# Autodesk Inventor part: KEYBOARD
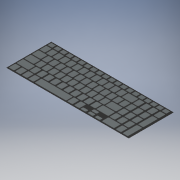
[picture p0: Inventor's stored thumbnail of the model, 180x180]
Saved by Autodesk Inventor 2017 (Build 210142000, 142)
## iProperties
Created: 2017-02
Part Number: KEYBOARD
Material: Generic
Document SubType Name: Modeling
Designer: Ali
Density: 1 g/cm^3
Appearance: Default
Author: Ali
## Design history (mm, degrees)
sketch "Sketch1"
  geometry: L1 (149.99, -109.99)-(-149.99, -109.99); L2 (-149.99, -109.99)-(-149.99, 0); L3 (-149.99, 0)-(149.99, 0); L4 (149.99, 0)-(149.99, -109.99)
  constraints: 8 end point, 2 parallel, 1 horizontal, 1 perpendicular
  dimensions: "d2" = 299.98 distance of L2.end L3.end; "d3" = 109.99 distance of L1.end L2.end
extrude "KEYBOARD BASE" new body sketch "Sketch1" distance "d4" = 0.01; taper "d5" = 0 deg
sketch "Sketch2"
  geometry: L1 (-146.991, 107.99)-(-136.991, 107.99); L2 (-135.991, 106.99)-(-135.991, 98.99); L3 (-136.991, 97.99)-(-146.991, 97.99); L4 (-147.991, 98.99)-(-147.991, 106.99); A1 r 1 centre (-146.991, 106.99) between (-146.991, 107.99) and (-147.991, 106.99); A2 r 1 centre (-136.991, 106.99) between (-135.991, 106.99) and (-136.991, 107.99); A3 r 1 centre (-136.991, 98.99) between (-136.991, 97.99) and (-135.991, 98.99); A4 r 1 centre (-146.991, 98.99) between (-147.991, 98.99) and (-146.991, 97.99); 5 further points
  constraints: 8 end point, 8 point on circle, 8 point on line, 8 tangent, 4 centre point, 3 equal radius, 2 parallel, 1 horizontal, 1 perpendicular
  dimensions: "d9" = 10 distance of point (-147.991, 97.99) point (-147.991, 107.99); "d10" = 12 distance of point (-147.991, 107.99) point (-135.991, 107.99); "d150" = 1 radius of A1 (derived)
extrude "ESCAPE BUTTON" join sketch "Sketch2" distance "d11" = 0.3; taper "d12" = 0 deg
sketch "Sketch3"
  geometry: L1 (-145.991, 95.99)-(-136.491, 95.99); L2 (-134.491, 93.99)-(-134.491, 80.79); L3 (-136.491, 78.79)-(-145.991, 78.79); L4 (-147.991, 80.79)-(-147.991, 93.99); A1 r 2 centre (-145.991, 93.99) between (-145.991, 95.99) and (-147.991, 93.99); A2 r 2 centre (-136.491, 93.99) between (-134.491, 93.99) and (-136.491, 95.99); A3 r 2 centre (-136.491, 80.79) between (-136.491, 78.79) and (-134.491, 80.79); A4 r 2 centre (-145.991, 80.79) between (-147.991, 80.79) and (-145.991, 78.79); 4 further points
  constraints: 8 end point, 8 point on circle, 8 point on line, 8 tangent, 4 centre point, 3 equal radius, 2 parallel, 1 horizontal, 1 perpendicular
  dimensions: "d19" = 13.5 distance of point (-147.991, 95.99) point (-134.491, 95.99); "d20" = 17.2 distance of point (-147.991, 78.79) point (-147.991, 95.99); "d151" = 2 radius of A1 (derived)
extrude "2ND ROW" join sketch "Sketch3" distance "d21" = 0.3; taper "d22" = 0 deg
pattern_linear "2ND ROW PATTERN" dims "d25" = 15.5
sketch "Sketch6"
  geometry: L1 (133.509, 95.99)-(143.009, 95.99); L2 (145.009, 93.99)-(145.009, 80.79); L3 (143.009, 78.79)-(133.509, 78.79); L4 (131.509, 80.79)-(131.509, 93.99); A1 r 2 centre (133.509, 93.99) between (133.509, 95.99) and (131.509, 93.99); A2 r 2 centre (143.009, 93.99) between (145.009, 93.99) and (143.009, 95.99); A3 r 2 centre (143.009, 80.79) between (143.009, 78.79) and (145.009, 80.79); A4 r 2 centre (133.509, 80.79) between (131.509, 80.79) and (133.509, 78.79); 5 further points
  constraints: 8 end point, 8 point on circle, 8 point on line, 8 tangent, 4 centre point, 3 equal radius, 2 parallel, 1 horizontal, 1 perpendicular
  dimensions: "d52" = 13.5 distance of point (145.009, 78.79) point (131.509, 78.79); "d53" = 17.2 distance of point (145.009, 95.99) point (145.009, 78.79); "d157" = 2 radius of A1 (derived)
extrude "BACKSPACE BUTTON" join sketch "Sketch6" distance "d33" = 0.3; taper "d34" = 0 deg
sketch "Sketch7"
  geometry: L1 (133.51, 76.99)-(143.01, 76.99); L2 (145.01, 74.99)-(145.01, 42.79); L3 (143.01, 40.79)-(133.51, 40.79); L4 (131.51, 42.79)-(131.51, 74.99); A1 r 2 centre (133.51, 74.99) between (133.51, 76.99) and (131.51, 74.99); A2 r 2 centre (143.01, 74.99) between (145.01, 74.99) and (143.01, 76.99); A3 r 2 centre (143.01, 42.79) between (143.01, 40.79) and (145.01, 42.79); A4 r 2 centre (133.51, 42.79) between (131.51, 42.79) and (133.51, 40.79); 5 further points
  constraints: 8 end point, 8 point on circle, 8 point on line, 8 tangent, 4 centre point, 3 equal radius, 2 parallel, 1 horizontal, 1 perpendicular
  dimensions: "d56" = 13.5 distance of point (145.01, 40.79) point (131.51, 40.79); "d57" = 36.2 distance of point (145.01, 76.99) point (145.01, 40.79); "d158" = 2 radius of A1 (derived)
extrude "NUM LOCK BUTTON" join sketch "Sketch7" distance "d38" = 0.3; taper "d39" = 0 deg
pattern_linear "NUMERIC KEYPAD" dims "d42" = 17, "d45" = 19
sketch "Sketch9"
  geometry: L1 (116.509, 19.989)-(126.009, 19.989); L2 (128.009, 17.989)-(128.009, 4.789); L3 (126.009, 2.789)-(116.509, 2.789); L4 (114.509, 4.789)-(114.509, 17.989); A1 r 2 centre (116.509, 17.989) between (116.509, 19.989) and (114.509, 17.989); A2 r 2 centre (126.009, 17.989) between (128.009, 17.989) and (126.009, 19.989); A3 r 2 centre (126.009, 4.789) between (126.009, 2.789) and (128.009, 4.789); A4 r 2 centre (116.509, 4.789) between (114.509, 4.789) and (116.509, 2.789); 5 further points
  constraints: 8 end point, 8 point on circle, 8 point on line, 8 tangent, 4 centre point, 3 equal radius, 2 parallel, 1 horizontal, 1 perpendicular
  dimensions: "d160" = 2 radius of A1 (derived)
extrude "SUBTRACT BUTTON" join sketch "Sketch9" distance "d54" = 0.3; taper "d55" = 0 deg
sketch "Sketch10"
  geometry: L1 (-145.991, 76.986)-(-127.991, 76.986); L2 (-125.991, 74.986)-(-125.991, 61.786); L3 (-127.991, 59.786)-(-145.991, 59.786); L4 (-147.991, 61.786)-(-147.991, 74.986); A1 r 2 centre (-145.991, 74.986) between (-145.991, 76.986) and (-147.991, 74.986); A2 r 2 centre (-127.991, 74.986) between (-125.991, 74.986) and (-127.991, 76.986); A3 r 2 centre (-127.991, 61.786) between (-127.991, 59.786) and (-125.991, 61.786); A4 r 2 centre (-145.991, 61.786) between (-147.991, 61.786) and (-145.991, 59.786); 4 further points
  constraints: 8 end point, 8 point on circle, 8 point on line, 8 tangent, 4 centre point, 3 equal radius, 2 parallel, 1 horizontal, 1 perpendicular
  dimensions: "d161" = 2 radius of A1 (derived)
extrude "ADD BUTTON" join sketch "Sketch10" distance "d58" = 0.3; taper "d59" = 0 deg
pattern_linear "ENTER BUTTON" dims "d62" = 38
sketch "Sketch11"
  geometry: L1 (-121.995, 76.986)-(-112.495, 76.986); L2 (-110.495, 74.986)-(-110.495, 61.786); L3 (-112.495, 59.786)-(-121.995, 59.786); L4 (-123.995, 61.786)-(-123.995, 74.986); A1 r 2 centre (-121.995, 74.986) between (-121.995, 76.986) and (-123.995, 74.986); A2 r 2 centre (-112.495, 74.986) between (-110.495, 74.986) and (-112.495, 76.986); A3 r 2 centre (-112.495, 61.786) between (-112.495, 59.786) and (-110.495, 61.786); A4 r 2 centre (-121.995, 61.786) between (-123.995, 61.786) and (-121.995, 59.786); 5 further points
  constraints: 8 end point, 8 point on circle, 8 point on line, 8 tangent, 4 centre point, 3 equal radius, 2 parallel, 1 horizontal, 1 perpendicular
  dimensions: "d153" = 2 radius of A1 (derived)
extrude "0 BUTTON" join sketch "Sketch11" distance "d65" = 0.3; taper "d66" = 0 deg
sketch "Sketch12"
  geometry: L1 (-145.991, 57.989)-(-125.991, 57.989); L2 (-123.991, 55.989)-(-123.991, 42.789); L3 (-125.991, 40.789)-(-145.991, 40.789); L4 (-147.991, 42.789)-(-147.991, 55.989); A1 r 2 centre (-145.991, 55.989) between (-145.991, 57.989) and (-147.991, 55.989); A2 r 2 centre (-145.991, 42.789) between (-147.991, 42.789) and (-145.991, 40.789); A3 r 2 centre (-125.991, 42.789) between (-125.991, 40.789) and (-123.991, 42.789); A4 r 2 centre (-125.991, 55.989) between (-123.991, 55.989) and (-125.991, 57.989); 4 further points
  constraints: 8 end point, 8 point on circle, 8 point on line, 8 tangent, 4 centre point, 3 equal radius, 2 parallel, 1 horizontal, 1 perpendicular
  dimensions: "d84" = 24 distance of point (-147.991, 57.989) point (-123.991, 57.989); "d85" = 17.2 distance of point (-147.991, 40.789) point (-147.991, 57.989); "d162" = 2 radius of A1 (derived)
extrude "DOT BUTTON" join sketch "Sketch12" distance "d69" = 0.3; taper "d70" = 0 deg
sketch "Sketch13"
  geometry: L1 (-119.996, 57.989)-(-110.496, 57.989); L2 (-108.496, 55.989)-(-108.496, 42.789); L3 (-110.496, 40.789)-(-119.996, 40.789); L4 (-121.996, 42.789)-(-121.996, 55.989); A1 r 2 centre (-119.996, 55.989) between (-119.996, 57.989) and (-121.996, 55.989); A2 r 2 centre (-110.496, 55.989) between (-108.496, 55.989) and (-110.496, 57.989); A3 r 2 centre (-110.496, 42.789) between (-110.496, 40.789) and (-108.496, 42.789); A4 r 2 centre (-119.996, 42.789) between (-121.996, 42.789) and (-119.996, 40.789); 5 further points
  constraints: 8 end point, 8 point on circle, 8 point on line, 8 tangent, 4 centre point, 3 equal radius, 2 parallel, 1 horizontal, 1 perpendicular
  dimensions: "d154" = 2 radius of A1 (derived)
extrude "TAB BUTTON" join sketch "Sketch13" distance "d73" = 0.3; taper "d74" = 0 deg
sketch "Sketch14"
  geometry: L1 (52.999, 57.989)-(75.999, 57.989); L2 (77.999, 55.989)-(77.999, 42.789); L3 (75.999, 40.789)-(52.999, 40.789); L4 (50.999, 42.789)-(50.999, 55.989); A1 r 2 centre (52.999, 55.989) between (52.999, 57.989) and (50.999, 55.989); A2 r 2 centre (75.999, 55.989) between (77.999, 55.989) and (75.999, 57.989); A3 r 2 centre (75.999, 42.789) between (75.999, 40.789) and (77.999, 42.789); A4 r 2 centre (52.999, 42.789) between (50.999, 42.789) and (52.999, 40.789); 4 further points
  constraints: 8 end point, 8 point on circle, 8 point on line, 8 tangent, 4 centre point, 3 equal radius, 2 parallel, 1 horizontal, 1 perpendicular
  dimensions: "d95" = 27 distance of point (77.999, 40.789) point (50.999, 40.789); "d96" = 17.2 distance of point (77.999, 57.989) point (77.999, 40.789); "d163" = 2 radius of A1 (derived)
extrude "Q BUTTON" join sketch "Sketch14" distance "d77" = 0.3; taper "d78" = 0 deg
pattern_linear "QWERTY" dims "d81" = 15.7
sketch "Sketch15" dims "d112" = 17.2, "d113" = 77.5, "d165" = 2 (derived)
  geometry: L1 (-145.991, 38.992)-(-119.991, 38.992); L2 (-117.991, 36.992)-(-117.991, 23.792); L3 (-119.991, 21.792)-(-145.991, 21.792); L4 (-147.991, 23.792)-(-147.991, 36.992); A1 r 2 centre (-145.991, 36.992) between (-145.991, 38.992) and (-147.991, 36.992); A2 r 2 centre (-119.991, 36.992) between (-117.991, 36.992) and (-119.991, 38.992); A3 r 2 centre (-119.991, 23.792) between (-119.991, 21.792) and (-117.991, 23.792); A4 r 2 centre (-145.991, 23.792) between (-147.991, 23.792) and (-145.991, 21.792); 4 further points
  constraints: 8 end point, 8 point on circle, 8 point on line, 8 tangent, 4 centre point, 3 equal radius, 2 parallel, 1 horizontal, 1 perpendicular
  dimensions: "d101" = 30 distance of point (-147.991, 38.992) point (-117.991, 38.992); "d102" = 17.2 distance of point (-147.991, 21.792) point (-147.991, 38.992); "d164" = 2 radius of A1 (derived)
extrude "CAPS LOCK" join sketch "Sketch15" distance "d86" = 0.3; taper "d87" = 0 deg
sketch "Sketch16"
  geometry: L1 (-113.99, 38.992)-(-104.49, 38.992); L2 (-102.49, 36.992)-(-102.49, 23.792); L3 (-104.49, 21.792)-(-113.99, 21.792); L4 (-115.99, 23.792)-(-115.99, 36.992); A1 r 2 centre (-113.99, 36.992) between (-113.99, 38.992) and (-115.99, 36.992); A2 r 2 centre (-104.49, 36.992) between (-102.49, 36.992) and (-104.49, 38.992); A3 r 2 centre (-104.49, 23.792) between (-104.49, 21.792) and (-102.49, 23.792); A4 r 2 centre (-113.99, 23.792) between (-115.99, 23.792) and (-113.99, 21.792); 5 further points
  constraints: 8 end point, 8 point on circle, 8 point on line, 8 tangent, 4 centre point, 3 equal radius, 2 parallel, 1 horizontal, 1 perpendicular
  dimensions: "d155" = 2 radius of A1 (derived)
extrude "A BUTTON" join sketch "Sketch16" distance "d90" = 0.3; taper "d91" = 0 deg
pattern_linear "ASDFGH" dims "d94" = 15.75
sketch "Sketch17"
  geometry: L1 (-81.99, 19.989)-(-8.49, 19.989); L2 (-6.49, 17.989)-(-6.49, 4.789); L3 (-8.49, 2.789)-(-81.99, 2.789); L4 (-83.99, 4.789)-(-83.99, 17.989); A1 r 2 centre (-81.99, 17.989) between (-81.99, 19.989) and (-83.99, 17.989); A2 r 2 centre (-8.49, 17.989) between (-6.49, 17.989) and (-8.49, 19.989); A3 r 2 centre (-8.49, 4.789) between (-8.49, 2.789) and (-6.49, 4.789); A4 r 2 centre (-81.99, 4.789) between (-83.99, 4.789) and (-81.99, 2.789); 4 further points
  constraints: 8 end point, 8 point on circle, 8 point on line, 8 tangent, 4 centre point, 3 equal radius, 2 parallel, 1 horizontal, 1 perpendicular
  dimensions: "d112" = 17.2 distance of point (-6.49, 19.989) point (-6.49, 2.789); "d113" = 77.5 distance of point (-6.49, 2.789) point (-83.99, 2.789); "d165" = 2 radius of A1 (derived)
extrude "ENTER BUTTON 1" join sketch "Sketch17" distance "d97" = 0.3; taper "d98" = 0 deg
sketch "Sketch18"
  geometry: L1 (75.999, 38.991)-(49.999, 38.991); L2 (47.999, 36.991)-(47.999, 23.791); L3 (49.999, 21.791)-(75.999, 21.791); L4 (77.999, 23.791)-(77.999, 36.991); A1 r 2 centre (49.999, 36.991) between (49.999, 38.991) and (47.999, 36.991); A2 r 2 centre (75.999, 36.991) between (77.999, 36.991) and (75.999, 38.991); A3 r 2 centre (75.999, 23.791) between (75.999, 21.791) and (77.999, 23.791); A4 r 2 centre (49.999, 23.791) between (47.999, 23.791) and (49.999, 21.791); 4 further points
  constraints: 8 end point, 8 point on circle, 8 point on line, 8 tangent, 4 centre point, 3 equal radius, 2 parallel, 1 horizontal, 1 perpendicular
  dimensions: "d166" = 2 radius of A1 (derived)
extrude "LEFT SHIFT" join sketch "Sketch18" distance "d103" = 0.3; taper "d104" = 0 deg
sketch "Sketch19"
  geometry: L1 (-145.991, 19.992)-(-136.491, 19.992); L2 (-134.491, 17.992)-(-134.491, 4.792); L3 (-136.491, 2.792)-(-145.991, 2.792); L4 (-147.991, 4.792)-(-147.991, 17.992); A1 r 2 centre (-145.991, 17.992) between (-145.991, 19.992) and (-147.991, 17.992); A2 r 2 centre (-136.491, 17.992) between (-134.491, 17.992) and (-136.491, 19.992); A3 r 2 centre (-136.491, 4.792) between (-136.491, 2.792) and (-134.491, 4.792); A4 r 2 centre (-145.991, 4.792) between (-147.991, 4.792) and (-145.991, 2.792); 5 further points
  constraints: 8 end point, 8 point on circle, 8 point on line, 8 tangent, 4 centre point, 3 equal radius, 2 parallel, 1 horizontal, 1 perpendicular
  dimensions: "d167" = 2 radius of A1 (derived)
extrude "Z BUTTON" join sketch "Sketch19" distance "d107" = 0.3; taper "d108" = 0 deg
pattern_linear "ZXCVBN" dims "d111" = 16.5
sketch "Sketch20"
  geometry: L1 (-2.489, 19.989)-(7.011, 19.989); L2 (9.011, 17.989)-(9.011, 4.789); L3 (7.011, 2.789)-(-2.489, 2.789); L4 (-4.489, 4.789)-(-4.489, 17.989); A1 r 2 centre (-2.489, 17.989) between (-2.489, 19.989) and (-4.489, 17.989); A2 r 2 centre (7.011, 17.989) between (9.011, 17.989) and (7.011, 19.989); A3 r 2 centre (7.011, 4.789) between (7.011, 2.789) and (9.011, 4.789); A4 r 2 centre (-2.489, 4.789) between (-4.489, 4.789) and (-2.489, 2.789); 4 further points
  constraints: 8 end point, 8 point on circle, 8 point on line, 8 tangent, 4 centre point, 3 equal radius, 2 parallel, 1 horizontal, 1 perpendicular
  dimensions: "d168" = 2 radius of A1 (derived)
extrude "SPACE BAR" join sketch "Sketch20" distance "d114" = 0.3; taper "d115" = 0 deg
sketch "Sketch21"
  geometry: L1 (30.009, 2.789)-(39.509, 2.789); L2 (41.509, 4.789)-(41.509, 8.289); L3 (39.509, 10.289)-(30.009, 10.289); L4 (28.009, 8.289)-(28.009, 4.789); A1 r 2 centre (30.009, 8.289) between (30.009, 10.289) and (28.009, 8.289); A2 r 2 centre (39.509, 8.289) between (41.509, 8.289) and (39.509, 10.289); A3 r 2 centre (39.509, 4.789) between (39.509, 2.789) and (41.509, 4.789); A4 r 2 centre (30.009, 4.789) between (28.009, 4.789) and (30.009, 2.789); 4 further points
  constraints: 8 end point, 8 point on circle, 8 point on line, 8 tangent, 4 centre point, 3 equal radius, 2 parallel, 1 horizontal, 1 perpendicular
  dimensions: "d136" = 13.5 distance of point (28.009, 2.789) point (41.509, 2.789); "d137" = 7.5 distance of point (28.009, 10.289) point (28.009, 2.789); "d170" = 2 radius of A1 (derived)
extrude "RIGHT SHIFT" join sketch "Sketch21" distance "d118" = 0.3; taper "d119" = 0 deg
sketch "Sketch22"
  geometry: L1 (47.509, 12.085)-(57.009, 12.085); L2 (59.009, 14.085)-(59.009, 17.585); L3 (57.009, 19.585)-(47.509, 19.585); L4 (45.509, 17.585)-(45.509, 14.085); A1 r 2 centre (47.509, 17.585) between (47.509, 19.585) and (45.509, 17.585); A2 r 2 centre (57.009, 17.585) between (59.009, 17.585) and (57.009, 19.585); A3 r 2 centre (57.009, 14.085) between (57.009, 12.085) and (59.009, 14.085); A4 r 2 centre (47.509, 14.085) between (45.509, 14.085) and (47.509, 12.085); 5 further points
  constraints: 8 end point, 8 point on circle, 8 point on line, 8 tangent, 4 centre point, 3 equal radius, 2 parallel, 1 horizontal, 1 perpendicular
  dimensions: "d169" = 2 radius of A1 (derived)
extrude "CTRL BUTTON" join sketch "Sketch22" distance "d122" = 0.3; taper "d123" = 0 deg
pattern_linear "FN/WIN/ALT" dims "d126" = 16
extrude "ALT BUTTON" join sketch "Sketch20" distance "d129" = 0.3; taper "d130" = 0 deg
pattern_linear "CTRL RIGHT" dims "d133" = 17
extrude "LEFT ARROW KEY" join sketch "Sketch21" distance "d138" = 0.3; taper "d139" = 0 deg
pattern_linear "ARROW KEYS" dims "d145" = 17.5
extrude "UP ARROW KEY" join sketch "Sketch22" distance "d148" = 0.3; taper "d149" = 0 deg
body "Solid1"
pattern_linear "1ST ROW" dims "d15" = 14.75
sketch "Sketch4"
  geometry: L1 (55.509, 95.99)-(76.509, 95.99); L2 (78.509, 93.99)-(78.509, 80.79); L3 (76.509, 78.79)-(55.509, 78.79); L4 (53.509, 80.79)-(53.509, 93.99); A1 r 2 centre (55.509, 93.99) between (55.509, 95.99) and (53.509, 93.99); A2 r 2 centre (76.509, 93.99) between (78.509, 93.99) and (76.509, 95.99); A3 r 2 centre (76.509, 80.79) between (76.509, 78.79) and (78.509, 80.79); A4 r 2 centre (55.509, 80.79) between (53.509, 80.79) and (55.509, 78.79); 4 further points
  constraints: 8 end point, 8 point on circle, 8 point on line, 8 tangent, 4 centre point, 3 equal radius, 2 parallel, 1 horizontal, 1 perpendicular
  dimensions: "d31" = 25 distance of point (78.509, 78.79) point (53.509, 78.79); "d32" = 17.2 distance of point (78.509, 95.99) point (78.509, 78.79); "d156" = 2 radius of A1 (derived)
sketch "Sketch5"
  geometry: L1 (82.509, 95.99)-(92.009, 95.99); L2 (94.009, 93.99)-(94.009, 80.79); L3 (92.009, 78.79)-(82.509, 78.79); L4 (80.509, 80.79)-(80.509, 93.99); A1 r 2 centre (82.509, 93.99) between (82.509, 95.99) and (80.509, 93.99); A2 r 2 centre (92.009, 93.99) between (94.009, 93.99) and (92.009, 95.99); A3 r 2 centre (92.009, 80.79) between (92.009, 78.79) and (94.009, 80.79); A4 r 2 centre (82.509, 80.79) between (80.509, 80.79) and (82.509, 78.79); 4 further points
  constraints: 8 end point, 8 point on circle, 8 point on line, 8 tangent, 4 centre point, 3 equal radius, 2 parallel, 1 horizontal, 1 perpendicular
  dimensions: "d152" = 2 radius of A1 (derived)
sketch "Sketch8"
  geometry: L1 (82.509, 19.986)-(109.009, 19.986); L2 (111.009, 17.986)-(111.009, 4.786); L3 (109.009, 2.786)-(82.509, 2.786); L4 (80.509, 4.786)-(80.509, 17.986); A1 r 2 centre (82.509, 17.986) between (82.509, 19.986) and (80.509, 17.986); A2 r 2 centre (109.009, 17.986) between (111.009, 17.986) and (109.009, 19.986); A3 r 2 centre (109.009, 4.786) between (109.009, 2.786) and (111.009, 4.786); A4 r 2 centre (82.509, 4.786) between (80.509, 4.786) and (82.509, 2.786); 5 further points
  constraints: 8 end point, 8 point on circle, 8 point on line, 8 tangent, 4 centre point, 3 equal radius, 2 parallel, 1 horizontal, 1 perpendicular
  dimensions: "d63" = 30.5 distance of point (111.009, 2.786) point (80.509, 2.786); "d64" = 17.2 distance of point (111.009, 19.986) point (111.009, 2.786); "d159" = 2 radius of A1 (derived)
